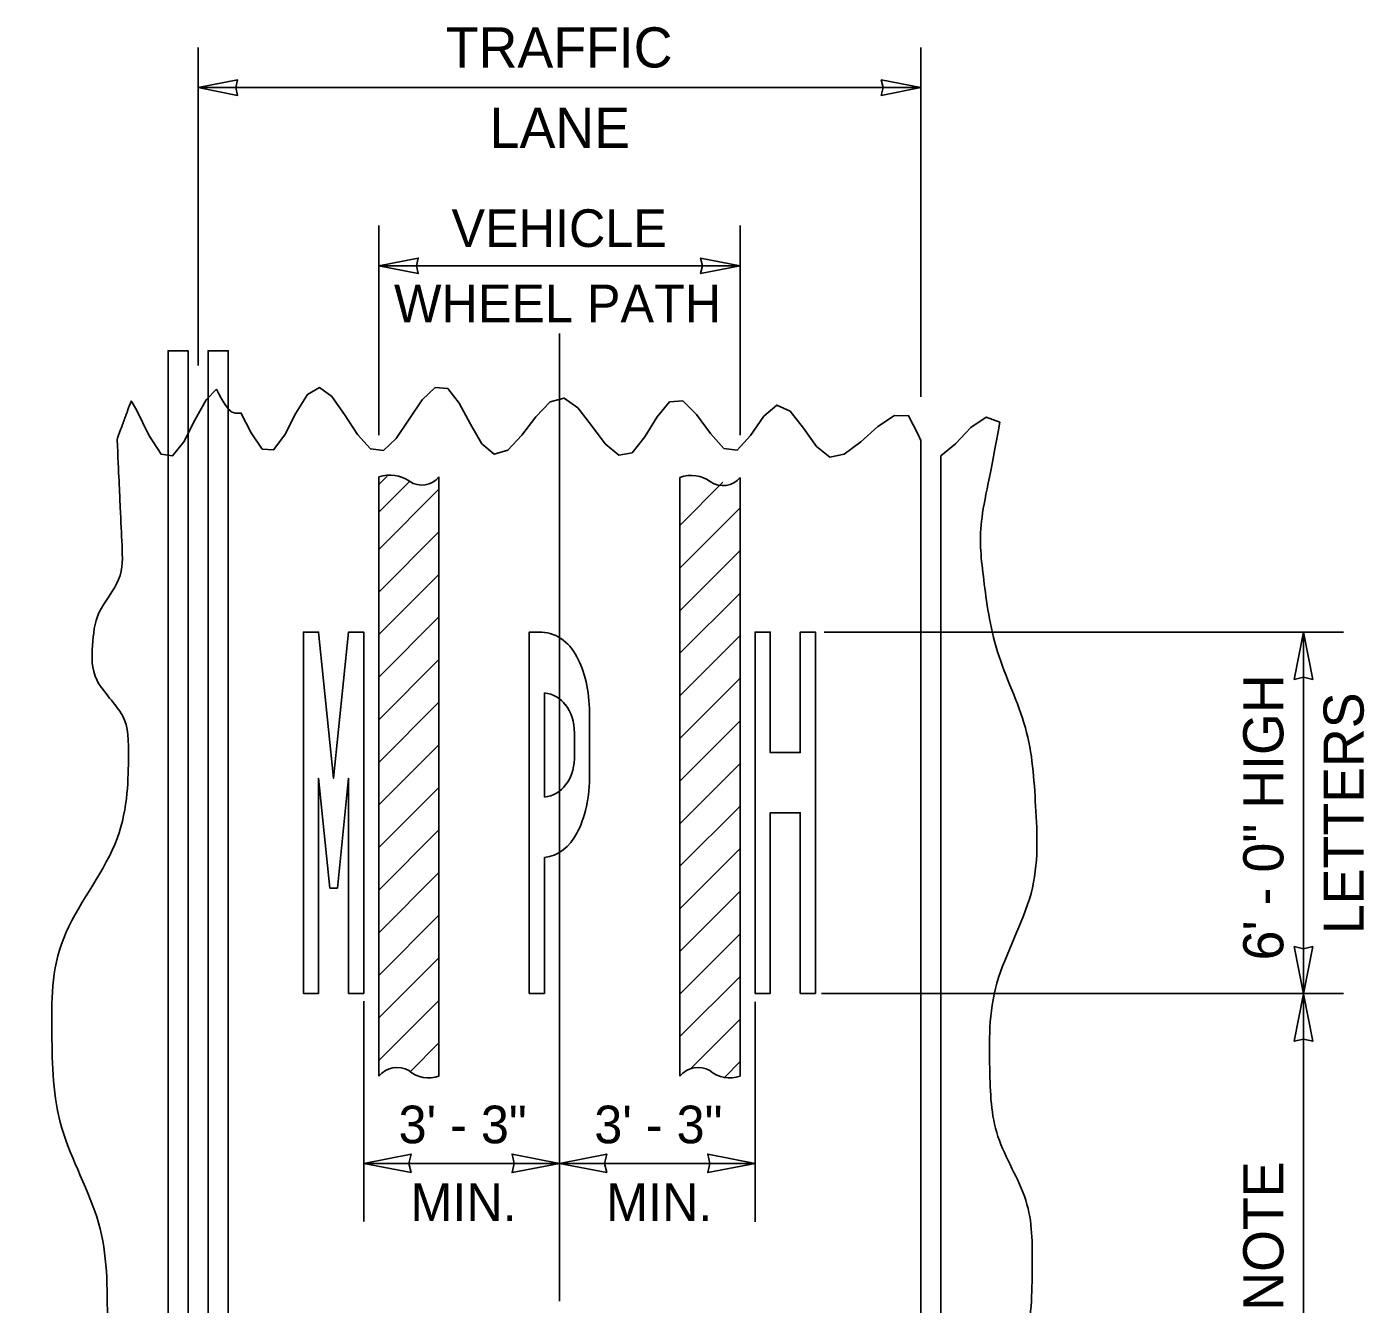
# Model space of a CAD drawing. Extents: x 99862 to 103151, y 100000 to 105076.
# Drawn here: x 101373 to 101906, y 100505 to 101013 of the extents above; entities that cross this region are included whole.
import ezdxf

# ---------------------------------------------------------------- set-up
doc = ezdxf.new("R2010")
doc.units = 0
for name, color, linetype in [('Level 15', 7, 'Continuous'), ('Level 2', 7, 'Continuous'), ('Level 20', 7, 'Continuous'), ('Level 6', 7, 'Continuous'), ('Level 7', 7, 'Continuous'), ('Level 8', 7, 'Continuous')]:
    doc.layers.add(name, color=color, linetype=linetype)

msp = doc.modelspace()

# ---------------------------------------------------------------- linework, layer by layer
at = {"layer": 'Level 15'}
for p, q in [((101441.71, 101005.23), (101441.71, 100878.51)), ((101729.71, 101005.23), (101729.71, 100866.05)), ((101441.71, 100989.23), (101729.71, 100989.23)), ((101513.71, 100850.81), (101513.71, 100934.23)), ((101657.71, 100850.81), (101657.71, 100934.23)), ((101513.71, 100918.23), (101657.71, 100918.23)), ((101585.71, 100891.31), (101585.71, 100680.15)), ((101576.71, 100772.34), (101573.71, 100772.34)), ((101573.71, 100772.34), (101573.71, 100628.34)), ((101577.47, 100772.34), (101576.71, 100772.34)), ((101691.17, 100772.34), (101898.23, 100772.34)), ((101882.23, 100772.34), (101882.23, 100628.18)), ((101579.71, 100706.5), (101579.71, 100748.17)), ((101597.7, 100715.81), (101597.71, 100740.26)), ((101591.71, 100731.19), (101591.71, 100721.76)), ((101579.71, 100628.34), (101579.71, 100682.46)), ((101585.71, 100680.15), (101585.71, 100505.74)), ((101507.71, 100625.34), (101507.71, 100537.55)), ((101573.71, 100628.34), (101579.71, 100628.34)), ((101663.71, 100625.08), (101663.71, 100537.38)), ((101690.17, 100628.34), (101898.23, 100628.34)), ((101882.23, 100628.18), (101882.23, 100388.18)), ((101585.71, 100560.66), (101507.71, 100560.66)), ((101585.71, 100560.66), (101663.71, 100560.66))]:
    msp.add_line(p, q, dxfattribs=at)
for points in [[(101441.71, 100989.23), (101457.43, 100986.14), (101456.71, 100989.23), (101457.43, 100992.31)], [(101729.71, 100989.23), (101713.98, 100986.14), (101714.71, 100989.23), (101713.98, 100992.31)], [(101513.71, 100918.23), (101529.43, 100915.14), (101528.71, 100918.23), (101529.43, 100921.31)], [(101657.71, 100918.23), (101641.98, 100915.14), (101642.71, 100918.23), (101641.98, 100921.31)], [(101501.71, 100714.06), (101501.71, 100628.34), (101507.71, 100628.34), (101507.71, 100772.34), (101501.71, 100772.34), (101495.71, 100714.06), (101489.71, 100772.34), (101483.71, 100772.34), (101483.71, 100628.34), (101489.71, 100628.34), (101489.71, 100714.06), (101494.21, 100670.34), (101497.21, 100670.34)], [(101681.71, 100724.34), (101669.71, 100724.34), (101669.71, 100772.34), (101663.71, 100772.34), (101663.71, 100628.34), (101669.71, 100628.34), (101669.71, 100700.34), (101681.71, 100700.34), (101681.71, 100628.34), (101687.71, 100628.34), (101687.71, 100772.34), (101681.71, 100772.34)], [(101882.23, 100772.34), (101878.53, 100753.47), (101882.23, 100754.35), (101885.93, 100753.47)], [(101882.23, 100628.18), (101878.53, 100647.05), (101882.23, 100646.17), (101885.93, 100647.05)], [(101882.23, 100628.18), (101878.53, 100609.31), (101882.23, 100610.18), (101885.93, 100609.31)], [(101507.71, 100560.66), (101526.58, 100556.96), (101525.71, 100560.66), (101526.58, 100564.36)], [(101585.71, 100560.66), (101566.84, 100556.96), (101567.71, 100560.66), (101566.84, 100564.36)], [(101585.71, 100560.66), (101604.58, 100556.96), (101603.71, 100560.66), (101604.58, 100564.36)], [(101663.71, 100560.66), (101644.84, 100556.96), (101645.71, 100560.66), (101644.84, 100564.36)]]:
    msp.add_lwpolyline(points, close=True, dxfattribs=at)
for centre, major_axis, ratio, start_param, end_param in [((101577.75, 100753.1), (0, -19.25), 0.883106, 2.078693, 3.158066), ((101583.45, 100739.84), (0, -29.47), 0.483719, 1.584917, 2.445445), ((101577.51, 100738.77), (12.05, 0), 0.792657, 0.505828, 1.38755), ((101581.53, 100732.1), (0, -14.73), 0.691027, 1.570796, 2.445559), ((101581.53, 100732.1), (0, -14.73), 0.691027, 1.529951, 1.570796), ((101581.53, 100731.46), (0.92, -14.68), 0.691023, 1.508615, 1.52981), ((101581.59, 100722.55), (-0.04, -14.68), 0.690438, 0.696034, 1.518966), ((101583.46, 100714.83), (0, -29.48), 0.483307, 0.696034, 1.604189), ((101577.51, 100715.91), (12.05, 0), 0.793333, 4.895635, 5.777357), ((101577.83, 100701.47), (0, -19.13), 0.882353, 0.111341, 1.064968), ((101521.04, 100587.81), (0, -11.05), 0.917809, 2.66324, 3.950242), ((101533.54, 100608.52), (0, -13.84), 0.917809, 5.61869, 6.617383), ((101641.04, 100587.82), (0, -11.04), 0.918519, 2.66324, 3.950242), ((101653.54, 100608.51), (0, -13.83), 0.918519, 5.61869, 6.617383)]:
    msp.add_ellipse(centre, major_axis=major_axis, ratio=ratio, start_param=start_param, end_param=end_param, dxfattribs=at)
at = {"layer": 'Level 2'}
for points in [[(101437.71, 100084.29), (101437.71, 100884.42), (101429.71, 100884.42), (101429.71, 100084.29), (101437.71, 100084.29)], [(101437.71, 100884.42), (101429.71, 100884.42), (101429.71, 100084.29)], [(101453.71, 100084.29), (101453.71, 100884.42), (101445.71, 100884.42), (101445.71, 100084.29), (101453.71, 100084.29)], [(101453.71, 100884.42), (101445.71, 100884.42), (101445.71, 100084.29)]]:
    msp.add_lwpolyline(points, dxfattribs=at)
at = {"layer": 'Level 6'}
for p, q in [((101729.71, 100121.05), (101729.71, 100847.98)), ((101737.71, 100111.06), (101737.71, 100842.4)), ((101513.54, 100819.97), (101526.07, 100832.5)), ((101513.71, 100831.11), (101517.09, 100834.49)), ((101633.64, 100814.8), (101650.89, 100832.04)), ((101513.71, 100805.25), (101537.71, 100829.25)), ((101633.71, 100797.81), (101657.71, 100821.81)), ((101513.71, 100788.28), (101537.71, 100812.28)), ((101633.71, 100780.84), (101657.71, 100804.84)), ((101513.71, 100771.31), (101537.71, 100795.31)), ((101633.71, 100763.87), (101657.71, 100787.87)), ((101513.71, 100754.34), (101537.71, 100778.34)), ((101633.71, 100746.9), (101657.71, 100770.9)), ((101513.71, 100737.37), (101537.71, 100761.37)), ((101633.71, 100729.93), (101657.71, 100753.93)), ((101513.71, 100720.4), (101537.71, 100744.4)), ((101633.71, 100712.96), (101657.71, 100736.96)), ((101513.71, 100703.43), (101537.71, 100727.43)), ((101633.71, 100695.99), (101657.71, 100719.99)), ((101513.71, 100686.46), (101537.71, 100710.46)), ((101633.71, 100679.02), (101657.71, 100703.02)), ((101513.71, 100669.49), (101537.71, 100693.49)), ((101633.71, 100662.05), (101657.71, 100686.05)), ((101513.71, 100652.52), (101537.71, 100676.52)), ((101633.71, 100645.08), (101657.71, 100669.08)), ((101513.71, 100635.55), (101537.71, 100659.55)), ((101633.71, 100628.11), (101657.71, 100652.11)), ((101513.71, 100618.58), (101537.71, 100642.58)), ((101633.71, 100611.14), (101657.71, 100635.14)), ((101513.71, 100601.61), (101537.71, 100625.61)), ((101637.63, 100598.09), (101657.71, 100618.17)), ((101526.31, 100597.24), (101537.71, 100608.64)), ((101651.43, 100594.92), (101657.71, 100601.2))]:
    msp.add_line(p, q, dxfattribs=at)
for points in [[(101445.71, 100865.76), (101445.71, 100094.22)], [(101453.71, 100100.59), (101453.71, 100862.27)], [(101437.71, 100092.97), (101437.71, 100851.99)], [(101429.71, 100843.17), (101429.71, 100110.43)], [(101513.71, 100834.14), (101513.71, 100595.44)], [(101537.71, 100595.44), (101537.71, 100834.14)], [(101633.71, 100833.94), (101633.71, 100595.44)], [(101657.71, 100595.44), (101657.71, 100833.94)]]:
    msp.add_lwpolyline(points, dxfattribs=at)
for centre, radius, start, end in [((101518.15, 100821.44), 13.45, 54.4864, 109.2534), ((101530.9, 100839.55), 8.7, 235.4073, 321.5349), ((101638.15, 100821.25), 13.45, 54.4864, 109.2534), ((101650.9, 100839.36), 8.7, 235.4073, 321.5349)]:
    msp.add_arc(centre, radius, start, end, dxfattribs=at)
for centre, major_axis, ratio, start_param, end_param in [((101521.04, 100587.81), (0, -11.05), 0.917809, 2.66324, 3.950242), ((101533.54, 100608.52), (0, -13.84), 0.917809, 5.61869, 6.617383), ((101641.04, 100587.82), (0, -11.04), 0.918519, 2.66324, 3.950242), ((101653.54, 100608.51), (0, -13.83), 0.918519, 5.61869, 6.617383)]:
    msp.add_ellipse(centre, major_axis=major_axis, ratio=ratio, start_param=start_param, end_param=end_param, dxfattribs=at)
at = {"layer": 'Level 7'}
for points in [[(101449.01, 100869.14), (101444.93, 100864.89), (101440.46, 100856.69), (101435.98, 100848.17), (101431.51, 100842.54), (101426.97, 100843.17), (101422.12, 100850.71), (101417.15, 100860.86), (101415.02, 100864.38)], [(101629.64, 100864.06), (101624.63, 100858.1), (101619.71, 100850.09), (101614.69, 100843.79), (101609.4, 100842.82), (101603.98, 100847.36), (101598.52, 100854.58), (101593.03, 100861.6), (101587.53, 100865.54), (101581.99, 100863.99), (101576.37, 100858.1), (101570.72, 100850.74), (101565.14, 100844.79), (101559.7, 100843.13), (101554.75, 100847.35), (101550.23, 100855.13), (101545.81, 100863.46), (101541.21, 100869.31), (101536.17, 100869.79), (101531.02, 100864.85), (101525.86, 100857.15), (101520.69, 100849.49), (101515.54, 100844.66), (101510.41, 100845.28), (101505.25, 100851.01), (101500.11, 100858.96), (101495.03, 100866.2), (101490.08, 100869.75), (101485.32, 100867), (101480.72, 100859.48), (101476.23, 100850.89), (101471.77, 100844.95), (101467.3, 100845.25), (101462.83, 100851.68), (101458.78, 100859.65)], [(101729.71, 100848.68), (101728.56, 100851.27), (101724.89, 100858.53), (101719.23, 100858.57), (101712.64, 100854.16), (101705.77, 100848.16), (101699.2, 100843.21), (101693.48, 100841.96), (101688.21, 100846.25), (101682.94, 100853.56), (101677.66, 100860.27), (101672.39, 100862.74), (101667.12, 100858.33), (101661.85, 100850.62), (101656.57, 100844.79), (101651.27, 100845.41), (101645.85, 100851.39), (101640.38, 100858.98), (101634.95, 100864.4), (101629.67, 100864.08)], [(101761.21, 100855.89), (101755.82, 100857.95), (101749.73, 100853.83), (101743.56, 100847.32), (101737.71, 100842.56)], [(101729.71, 100121.05), (101729.71, 100848.68)], [(101737.71, 100842.56), (101737.71, 100111.57)]]:
    msp.add_lwpolyline(points, dxfattribs=at)
for points, degree in [([(101458.78, 100859.65), (101458.37, 100859.55), (101457.96, 100859.49), (101457.55, 100859.49), (101454.73, 100859.51), (101451.85, 100863.51), (101449.01, 100869.14)], 3), ([(101415.02, 100864.38), (101413.16, 100859.28), (101411.29, 100854.19), (101409.43, 100849.09)], 2), ([(101629.67, 100864.08), (101629.66, 100864.07), (101629.65, 100864.06), (101629.64, 100864.06)], 2), ([(101737.71, 100111.57), (101747.62, 100100.76), (101756.98, 100091.91), (101759.83, 100102.4), (101765.6, 100123.54), (101763.58, 100134.98), (101762.44, 100162.64), (101761.05, 100188.22), (101754.69, 100213.9), (101754.63, 100239.38), (101754.59, 100259.39), (101769.16, 100277.99), (101770.24, 100297.91), (101772.46, 100338.81), (101754.75, 100380.61), (101755.93, 100421.47), (101756.89, 100454.49), (101773.86, 100487.49), (101774.14, 100520.32), (101774.36, 100545.98), (101757.81, 100571.38), (101757.23, 100597.06), (101756.43, 100632.4), (101777.51, 100668.27), (101775.44, 100703.71), (101773.66, 100734.3), (101758.4, 100764.4), (101754.63, 100794.75), (101752.16, 100814.63), (101757.61, 100835.3), (101761.21, 100855.89)], 3), ([(101409.43, 100849.09), (101410.08, 100835), (101410.73, 100820.91), (101411.38, 100806.82), (101412.02, 100793.05), (101400.57, 100780.26), (101399.67, 100767.15), (101398.71, 100753), (101414.16, 100739.08), (101413.98, 100724.88), (101413.51, 100687.78), (101382.96, 100650.51), (101383.42, 100612.37), (101383.87, 100574.66), (101405.66, 100536.94), (101405.53, 100499.22), (101405.34, 100445.89), (101372.97, 100392.56), (101374.31, 100339.24), (101375.13, 100306.75), (101399.26, 100275.46), (101398.7, 100242.99), (101398.16, 100211.6), (101386.32, 100179.69), (101384.72, 100141.53), (101383.46, 100121.39), (101381.86, 100110.62), (101389.92, 100093.69), (101395.92, 100075.14), (101413.14, 100119.22), (101421.14, 100127.72), (101428.44, 100126.34), (101431.23, 100093.49), (101439.34, 100092.39), (101450.14, 100090.94), (101472.64, 100124.02), (101482.27, 100122.92), (101490.73, 100121.96), (101495.67, 100090.62), (101504.38, 100084.99), (101515.07, 100083.97), (101526.29, 100129.05), (101536.89, 100128.52), (101547.17, 100128.02), (101556.12, 100081.73), (101566.81, 100081.49), (101577.7, 100081.25), (101592.87, 100126.36), (101604.53, 100125.92), (101613.45, 100125.59), (101621.71, 100086.04), (101630.54, 100086.5), (101639.56, 100086.97), (101649.16, 100125.3), (101659.15, 100125.92), (101668.34, 100126.5), (101683.89, 100095.32), (101694.27, 100096.9), (101703.82, 100098.36), (101707.91, 100127.85), (101716.38, 100129.83), (101719.53, 100130.56), (101724.34, 100126.57), (101729.71, 100121.05)], 3)]:
    msp.add_open_spline(points, degree=degree, dxfattribs=at)
at = {"layer": 'Level 8'}
for points in [[(101497.21, 100670.34), (101501.71, 100714.06), (101501.71, 100628.34), (101507.71, 100628.34), (101507.71, 100772.34), (101501.71, 100772.34), (101495.71, 100714.06), (101489.71, 100772.34), (101483.71, 100772.34), (101483.71, 100628.34), (101489.71, 100628.34), (101489.71, 100714.06), (101494.21, 100670.34), (101497.21, 100670.34)], [(101494.21, 100670.34), (101497.21, 100670.34), (101501.71, 100714.06), (101501.71, 100628.34), (101507.71, 100628.34), (101507.71, 100772.34), (101501.71, 100772.34), (101495.71, 100714.06), (101489.71, 100772.34), (101483.71, 100772.34), (101483.71, 100628.34), (101489.71, 100628.34), (101489.71, 100714.06), (101494.21, 100670.34)], [(101577.47, 100772.34), (101576.71, 100772.34), (101573.71, 100772.34), (101573.71, 100628.34), (101579.71, 100628.34), (101579.71, 100682.46)], [(101577.47, 100772.34), (101576.71, 100772.34), (101573.71, 100772.34), (101573.71, 100628.34), (101579.71, 100628.34), (101579.71, 100682.46)], [(101681.71, 100772.34), (101681.71, 100724.34), (101669.71, 100724.34), (101669.71, 100772.34), (101663.71, 100772.34), (101663.71, 100628.34), (101669.71, 100628.34), (101669.71, 100700.34), (101681.71, 100700.34), (101681.71, 100628.34), (101687.71, 100628.34), (101687.71, 100772.34), (101681.71, 100772.34)], [(101687.71, 100772.34), (101681.71, 100772.34), (101681.71, 100724.34), (101669.71, 100724.34), (101669.71, 100772.34), (101663.71, 100772.34), (101663.71, 100628.34), (101669.71, 100628.34), (101669.71, 100700.34), (101681.71, 100700.34), (101681.71, 100628.34), (101687.71, 100628.34), (101687.71, 100772.34)], [(101579.71, 100706.5), (101579.71, 100748.17)], [(101579.71, 100706.5), (101579.71, 100748.17)], [(101597.7, 100715.81), (101597.71, 100740.26)], [(101597.7, 100715.81), (101597.71, 100740.26)], [(101591.71, 100731.19), (101591.71, 100721.76)], [(101591.71, 100731.19), (101591.71, 100721.76)]]:
    msp.add_lwpolyline(points, dxfattribs=at)
for centre, major_axis, ratio, start_param, end_param in [((101577.75, 100753.1), (0, -19.25), 0.883106, 2.078693, 3.158066), ((101577.75, 100753.1), (0, -19.25), 0.883106, 2.078693, 3.158066), ((101583.45, 100739.84), (0, -29.47), 0.483719, 1.584917, 2.445445), ((101583.45, 100739.84), (0, -29.47), 0.483719, 1.584917, 2.445445), ((101577.51, 100738.77), (12.05, 0), 0.792657, 0.505828, 1.38755), ((101577.51, 100738.77), (12.05, 0), 0.792657, 0.505828, 1.38755), ((101581.53, 100732.1), (0, -14.73), 0.691027, 1.570796, 2.445559), ((101581.53, 100732.1), (0, -14.73), 0.691027, 1.570796, 2.445559), ((101581.53, 100732.1), (0, -14.73), 0.691027, 1.529951, 1.570796), ((101581.53, 100732.1), (0, -14.73), 0.691027, 1.529951, 1.570796), ((101581.53, 100731.46), (0.92, -14.68), 0.691023, 1.508615, 1.52981), ((101581.53, 100731.46), (0.92, -14.68), 0.691023, 1.508615, 1.52981), ((101581.59, 100722.55), (-0.04, -14.68), 0.690438, 0.696034, 1.518966), ((101581.59, 100722.55), (-0.04, -14.68), 0.690438, 0.696034, 1.518966), ((101583.46, 100714.83), (0, -29.48), 0.483307, 0.696034, 1.604189), ((101583.46, 100714.83), (0, -29.48), 0.483307, 0.696034, 1.604189), ((101577.51, 100715.91), (12.05, 0), 0.793333, 4.895635, 5.777357), ((101577.51, 100715.91), (12.05, 0), 0.793333, 4.895635, 5.777357), ((101577.83, 100701.47), (0, -19.13), 0.882353, 0.111341, 1.064968), ((101577.83, 100701.47), (0, -19.13), 0.882353, 0.111341, 1.064968)]:
    msp.add_ellipse(centre, major_axis=major_axis, ratio=ratio, start_param=start_param, end_param=end_param, dxfattribs=at)

# ---------------------------------------------------------------- texts
at = {"layer": 'Level 20'}
for s, height, rotation, p in [('TRAFFIC', 16, 360, (101540.44, 100997.23)), ('LANE', 16, 360, (101557.93, 100965.23)), ('VEHICLE', 15, 360, (101542.69, 100925.73)), ('WHEEL PATH', 15, 360, (101519.77, 100895.73)), ('6\' - 0" HIGH', 16, 90, (101874.23, 100641.51)), ('LETTERS', 16, 90, (101906.23, 100651.96)), ('3\' - 3"', 15, 360, (101521.6, 100568.66)), ('3\' - 3"', 15, 360, (101599.6, 100568.66)), ('SEE NOTE', 16, 90, (101874.23, 100453.24)), ('MIN.', 15, 360, (101526.34, 100537.66)), ('MIN.', 15, 360, (101604.34, 100537.66))]:
    msp.add_text(s, height=height, rotation=rotation, dxfattribs=at).set_placement(p)

doc.saveas('drawing.dxf')
